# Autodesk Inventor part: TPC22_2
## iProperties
Shininess: 64.0
Length Units: 11272
Angle Units: 11279
Time Units: 11290
Mass Units: 11286
Length Display Precision: 3
Angle Display Precision: 2
Compacted: True
Part Number: TPC22_2
Document SubType Name: Modeling
Created: 2004-08
Designer: Lori
Manufacturer: Standard
Standards Organization: Custom
Density: 0.0
Volumn: 0.0
Area: 0.0
PropertySet Name: Model Information
Control State: 0
Master: False
Checked Out: False
Author: Lori
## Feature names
1. Base1
